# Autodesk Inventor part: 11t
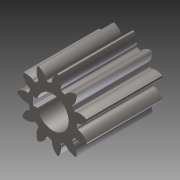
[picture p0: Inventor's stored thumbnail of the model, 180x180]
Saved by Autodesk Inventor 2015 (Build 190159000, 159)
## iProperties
Created: 2014-11
Part Number: 11t
Material: Steel
Document SubType Name: Modeling
Designer: Michael
Density: 7.85 g/cm^3
Appearance: Steel
Mass: 18.2383 g
Surface Area: 23.9266 cm^2
Volume: 2.32336 cm^3
Title: 217-3107-STEP.STEP
Description: STEP AP214
Creation Date: 2013-12-09
Sending System: SolidWorks 2013
Preprocessor: SwSTEP 2.0
Author: Michael
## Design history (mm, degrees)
node "11t1"
node "Split Line6"
node "Base1"
